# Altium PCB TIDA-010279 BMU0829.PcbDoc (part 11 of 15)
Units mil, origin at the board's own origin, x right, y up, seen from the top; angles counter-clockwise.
Board outline 11269.69 x 4438.98 mil, 4 copper layers (Top Layer, Signal Layer 1, Signal Layer 2, Bottom Layer), stack 61.6 mil thick; 1494 components, 725 nets, 3766 pads, 2728 vias.
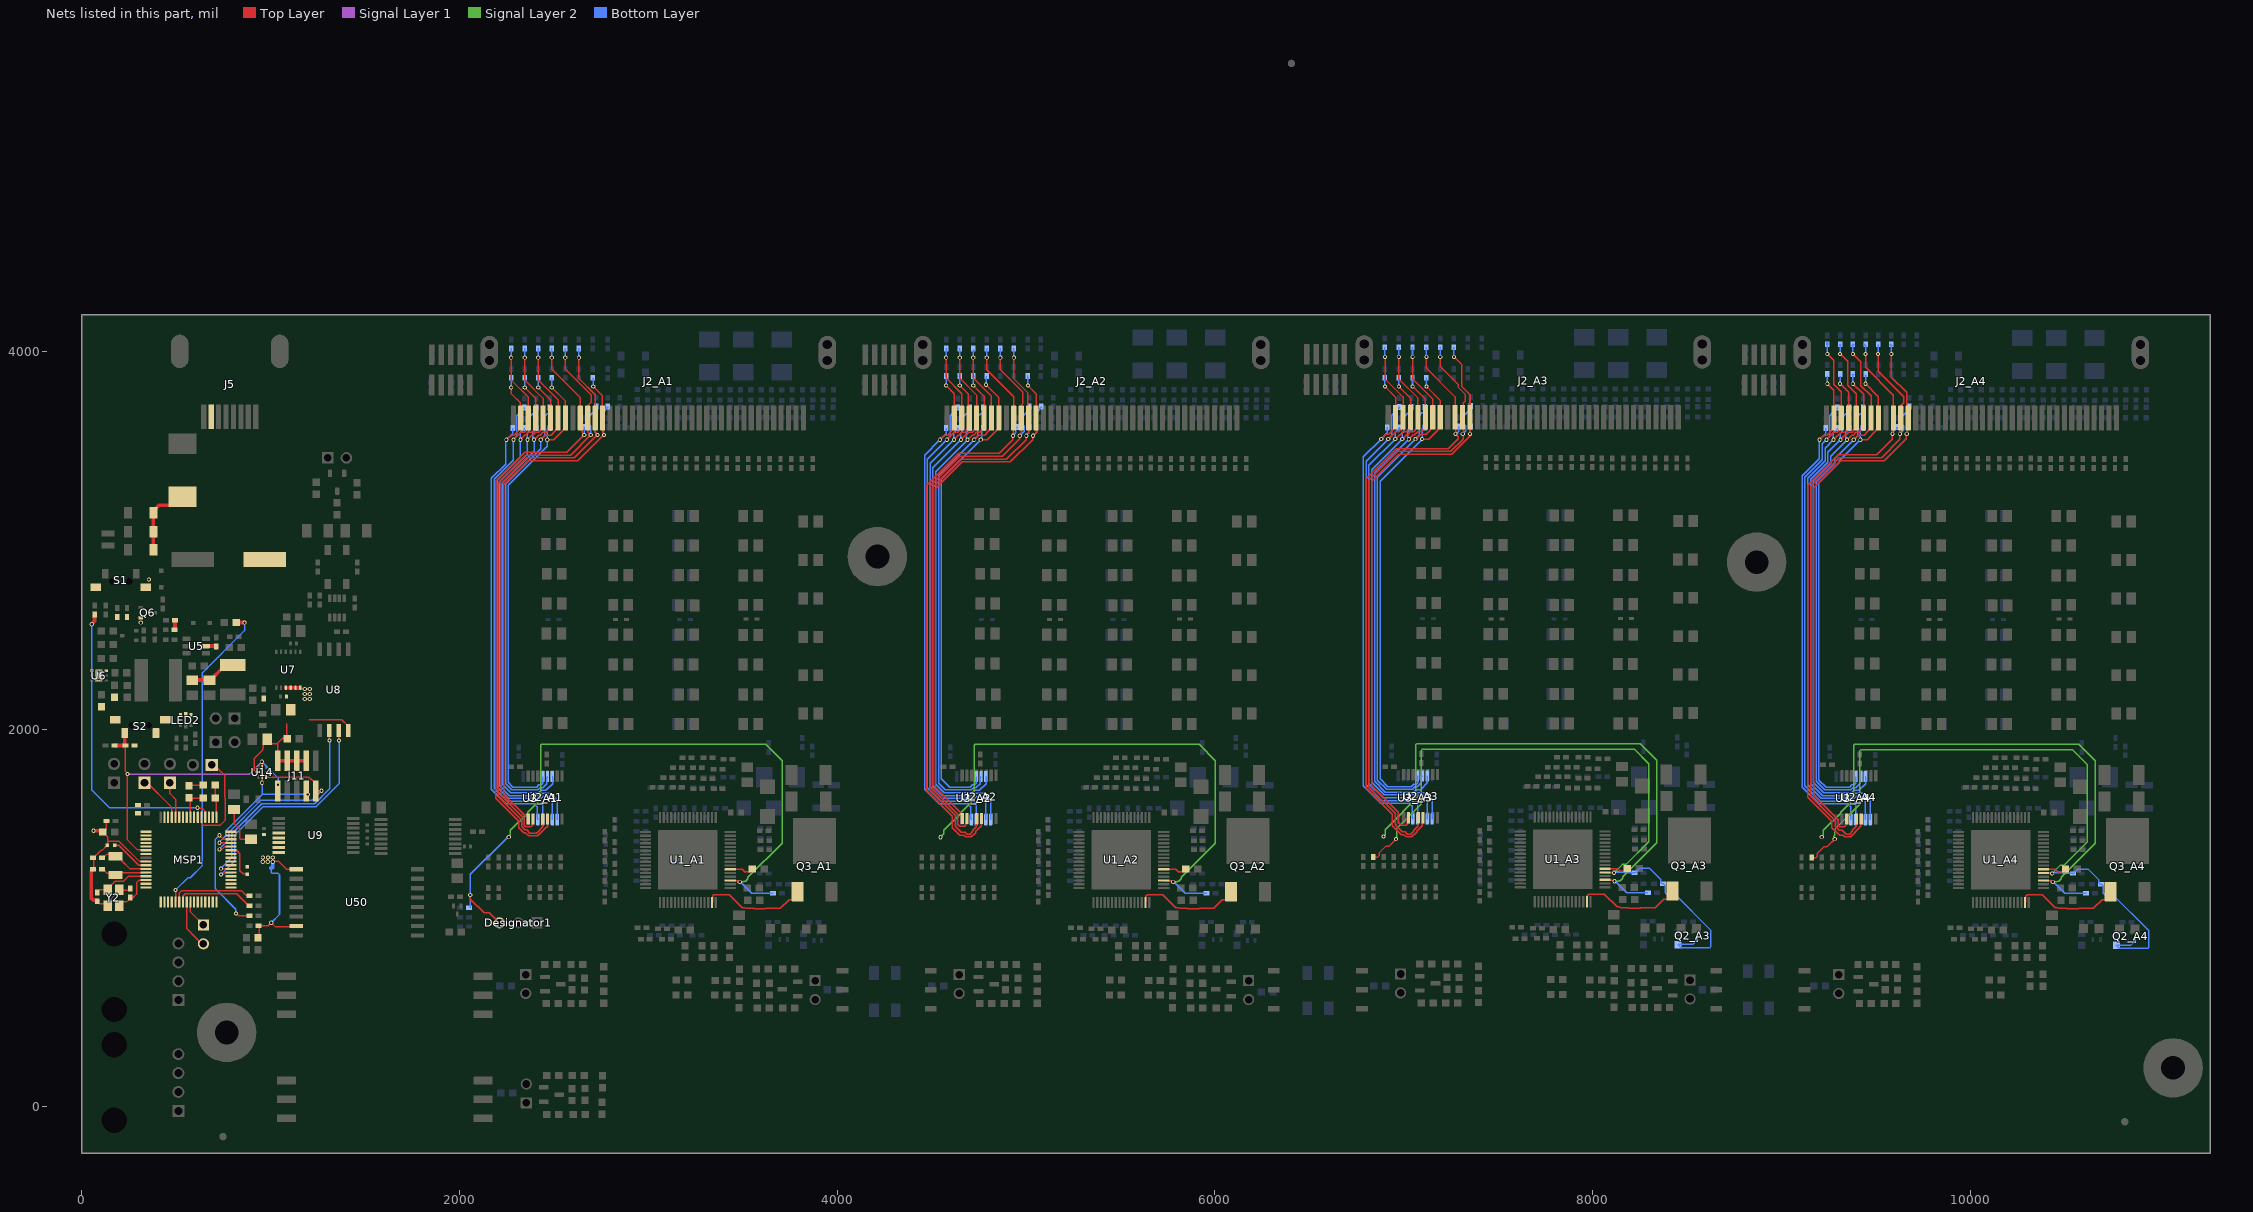
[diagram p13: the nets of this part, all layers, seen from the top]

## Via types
v1: diameter 22.01, hole 12.01, Top Layer to Bottom Layer, tented both sides, 2578 vias
v2: diameter 19.68, hole 7.87, Top Layer to Bottom Layer, tented both sides, 144 vias
v3: diameter 92.52, hole 49.21, Top Layer to Bottom Layer, 4 vias
v4: diameter 19.68, hole 7.87, Top Layer to Bottom Layer, 2 vias

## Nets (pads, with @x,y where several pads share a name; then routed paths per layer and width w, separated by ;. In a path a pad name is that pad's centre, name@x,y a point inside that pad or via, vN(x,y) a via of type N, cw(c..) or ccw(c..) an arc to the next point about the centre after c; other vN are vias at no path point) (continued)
NFAULT/GPIO2_A3: C114_A3.1 Q2_A3.1 R137_A3.2 R150_A3.1 R215_A3.1 U1_A3.53 | length 3719.8
  Top Layer w8: R150_A3.1@6838.78,1322.49 6862.59,1322.49 6868.99,1328.89 6868.99,1344.48 6905.51,1380.99 6922.32,1380.99 v1(6958.65,1417.32) ; U1_A3.53@8065.49,1241.27 8066.57,1240.18 8111.11,1240.18 v1(8112.2,1239.1)
  Signal Layer 2 w8: v1(6958.65,1417.32) 6961.33,1420 6961.33,1443.52 6962.13,1444.32 6962.13,1474.05 7093.31,1605.23 7093.31,1888.09 7098,1892.78 8220.8,1892.78 8296.87,1816.71 8296.87,1403.75 8176.47,1283.35 8156.97,1283.35 8112.72,1239.1 v1(8112.2,1239.1)
  Bottom Layer w8: v1(8112.2,1239.1) 8115.99,1239.1 8120.26,1243.37 8166.42,1243.37 8170.69,1239.1 8220.93,1239.1 C114_A3.1@8221.45,1238.57 8225.39,1238.57 8241.08,1254.26 8241.08,1255.3 8248.03,1262.26 8301.78,1262.26 8359.5,1204.55 8359.5,1188.83 8367.31,1181.02 8375.18,1181.02 8382.99,1173.21 8382.99,1134.2 8392.02,1125.17 8434.93,1125.17 8624.31,935.79 8624.31,846.46 8619.62,841.78 8468.85,841.78 8468.29,842.33 8467.31,842.33 8452.61,857.03 R137_A3.2@8452.61,858.01 8454.55,859.96 8529.58,859.96 8548.94,879.31 Q2_A3.1@8548.94,884.82
NFAULT/GPIO2_A4: C114_A4.1 Q2_A4.1 R137_A4.2 R150_A4.1 R215_A4.1 U1_A4.53 | length 3724.3
  Top Layer w8: R150_A4.1@9159.01,1319.29 9182.82,1319.29 9189.22,1325.68 9189.22,1341.27 9225.74,1377.79 9241.94,1377.79 v1(9281.48,1417.32) ; U1_A4.53@10385.72,1238.06 10386.8,1236.97 10431.34,1236.97 v1(10432.43,1235.89)
  Signal Layer 2 w8: v1(9281.48,1417.32) 9278.8,1420 9278.8,1429.03 9275.52,1432.31 9282.36,1439.16 9282.36,1470.84 9413.54,1602.02 9413.54,1884.88 9418.23,1889.57 10541.03,1889.57 10617.1,1813.51 10617.1,1400.54 10496.7,1280.14 10477.2,1280.14 10432.95,1235.89 v1(10432.43,1235.89)
  Bottom Layer w8: v1(10432.43,1235.89) 10436.22,1235.89 10440.49,1240.16 10486.64,1240.16 10490.92,1235.89 10541.16,1235.89 C114_A4.1@10541.68,1235.37 10545.62,1235.37 10561.31,1251.05 10561.31,1252.09 10568.26,1259.05 10622.01,1259.05 10679.73,1201.34 10679.73,1185.62 10687.54,1177.81 10695.41,1177.81 10703.22,1170 10703.22,1130.99 10712.25,1121.96 10755.16,1121.96 10944.53,932.59 10944.53,843.25 10939.85,838.57 10789.08,838.57 10788.52,839.12 10787.54,839.12 10772.84,853.82 R137_A4.2@10772.84,854.81 10774.78,856.75 10849.81,856.75 10869.17,876.1 Q2_A4.1@10869.17,881.62
NPNB_A1: Q3_A1.1 U1_A1.47 | length 564.5
  Top Layer w7: U1_A1.47@3337.42,1082.55 3339.83,1084.95 3339.83,1115.64 3347.63,1123.45 3429.04,1123.45 3497.52,1054.96 3510.72,1054.96 3515.13,1050.55 3558.12,1050.55 3559.79,1048.88 3620.9,1048.88 3622.57,1050.55 3698.29,1050.55 3744.79,1097.05 3762.29,1097.05 3790.29,1125.04 Q3_A1.1@3790.29,1139.33
NPNB_A2: Q3_A2.1 U1_A2.47 | length 564.5
  Top Layer w7: U1_A2.47@5632.44,1082.55 5634.84,1084.95 5634.84,1115.64 5642.65,1123.45 5724.05,1123.45 5792.54,1054.96 5805.74,1054.96 5810.15,1050.55 5853.13,1050.55 5854.8,1048.88 5915.92,1048.88 5917.59,1050.55 5993.31,1050.55 6039.81,1097.05 6057.31,1097.05 6085.3,1125.04 Q3_A2.1@6085.3,1139.33
NPNB_A3: Q3_A3.1 U1_A3.47 | length 564.5
  Top Layer w7: U1_A3.47@7969.03,1085.75 7971.44,1088.16 7971.44,1118.85 7979.24,1126.66 8060.65,1126.66 8129.14,1058.17 8142.33,1058.17 8146.74,1053.76 8189.73,1053.76 8191.4,1052.09 8252.51,1052.09 8254.18,1053.76 8329.91,1053.76 8376.4,1100.26 8393.9,1100.26 8421.9,1128.25 Q3_A3.1@8421.9,1142.54
NPNB_A4: Q3_A4.1 U1_A4.47 | length 564.5
  Top Layer w7: U1_A4.47@10289.26,1082.55 10291.67,1084.95 10291.67,1115.64 10299.47,1123.45 10380.88,1123.45 10449.37,1054.96 10462.56,1054.96 10466.97,1050.55 10509.96,1050.55 10511.63,1048.88 10572.74,1048.88 10574.41,1050.55 10650.13,1050.55 10696.63,1097.05 10714.13,1097.05 10742.13,1125.04 Q3_A4.1@10742.13,1139.33
PA0: MSP1.33
PA1: MSP1.34
PA2_ROSC: MSP1.42 R229.1 | length 219.4
  Top Layer w8: R229.1@175.65,1385.02 196.48,1385.02 228.37,1353.13 228.37,1352.69 301.61,1279.45 MSP1.42@351.04,1279.45
PA3_LFXIN: C174.2 MSP1.43 Y1.2 | length 287.8
  Top Layer w8: C174.2@106.77,1318.58 114.58,1326.4 123.28,1326.4 123.51,1326.63 123.51,1328.25 131.66,1336.4 179.1,1336.4 194.78,1320.72 200.69,1320.72 212.5,1308.9 212.5,1303 255.74,1259.76 MSP1.43@351.04,1259.76
PA4_LFXOUT: C177.2 MSP1.44 Y1.1 | length 256
  Top Layer w8: C177.2@106.77,1258.51 114.35,1250.93 123.51,1250.93 123.51,1246.99 132.53,1237.98 179.1,1237.98 181.2,1240.08 MSP1.44@351.04,1240.08
PA5_HFXIN: C176.2 MSP1.45 Y2.3 | length 319.5
  Top Layer w8: C176.2@82.99,1135.81 82.99,1139.75 93.52,1150.28 Y2.3@136.77,1150.28 136.77,1155.2 176.18,1194.61 221.42,1194.61 247.2,1220.39 MSP1.45@351.04,1220.39 ; C176.2@84.03,1136.85 89.17,1131.71 C176.2@89.17,1127.78
PA6_HFXOUT: C175.2 MSP1.46 Y2.1 | length 253.5
  Top Layer w8: Y2.1@199.76,1063.66 199.76,1066.54 218.4,1085.18 236.76,1085.18 255.91,1104.33 C175.2@255.91,1108.27 263.28,1100.9 269.67,1107.29 270.71,1107.29 290.28,1126.86 290.28,1187.14 301.95,1198.8 349.13,1198.8 MSP1.46@351.04,1200.71
PA7_CLK-OUT: MSP1.49
PA8_UART1-TX: MSP1.54 R253.1 | length 437.7
  Top Layer w8: MSP1.54@516.39,1083.95 517.31,1084.88 517.31,1132.61 528.26,1143.56 846.31,1143.56 868.64,1121.22 886.24,1121.22 R253.1@890.44,1117.03
PA9_UART1-RX: MSP1.55 R251.2 | length 414.3
  Top Layer w8: MSP1.55@536.08,1084.56 537.98,1086.47 537.98,1117.87 547.79,1127.68 820.38,1127.68 883.86,1064.2 R251.2@887.8,1064.2
PA10_UART0-TX: J16.2 MSP1.56 | length 269.7
  Top Layer w8: MSP1.56@555.76,1084.56 555.76,943.5 601.13,898.13 622.17,877.09 623.55,877.09 637.32,863.32 J16.2@651.13,863.32
PA11_UART0-RX: J16.1 MSP1.57 | length 149.8
  Top Layer w8: MSP1.57@575.45,1084.56 575.45,1032.22 J16.1@644.34,963.32
PA12_CAN-TX: MSP1.5 U8.3 | length 1255
  Top Layer w8: v1(737.05,1229.63) 739.73,1232.31 750.85,1232.31 756.71,1238.17 797.95,1238.17 MSP1.5@799.85,1240.08 ; U8.3@1360.2,1992.78 1361.28,1991.7 1361.28,1940.3 v1(1362.36,1939.22)
  Bottom Layer w8: v1(737.05,1229.63) 737.77,1229.63 810.12,1301.98 810.12,1439.62 959.41,1588.9 1240.1,1588.9 1362.36,1711.16 v1(1362.36,1939.22)
PA13_CAN-RX: MSP1.6 U8.2 | length 1195.7
  Top Layer w8: v1(737.05,1261.26) 738.55,1259.76 MSP1.6@790.01,1259.76 MSP1.6@799.85,1259.76 ; U8.2@1310.2,1992.78 1311.28,1991.7 1311.28,1940.3 v1(1312.36,1939.22)
  Bottom Layer w8: v1@737.87,1263.76 794.18,1320.07 794.18,1395.67 794.25,1395.74 794.25,1446.19 952.83,1604.78 1233.52,1604.78 1312.36,1683.61 v1(1312.36,1939.22)
PA14_TIMH0-C0: MSP1.7
PA15_DAC-OUT: MSP1.8
PA16_OPA1-OUT_ADC1.1: MSP1.9
PA17_OPA1-IN-_ADC1.2: MSP1.10
PA18_OPA1-IN+_ADC1.3_GPAMP-IN-: MSP1.11 R88.2 | length 164.8
  Top Layer w7: MSP1.11@816.93,1358.27 820.62,1358.27 837.86,1341.03 837.86,1250.92 855.64,1233.14 873.16,1233.14 R88.2@875.98,1230.32
PA19_SWDIO: J11.2 MSP1.12 U14.7 | length 1102.6
  Top Layer w8: v1@739.22,1363.16 742.34,1363.16 757.05,1377.87 MSP1.12@799.85,1377.87 ; U14.7@976.29,1746.24 976.29,1745.56 977.21,1744.64 1202.07,1744.64 1210.94,1735.77 1215.02,1735.77 1238.86,1711.93 J11.2@1238.86,1671.57 1240.55,1673.26 v1(1269.65,1673.26)
  Bottom Layer w8: v1@731.07,1369.02 732.67,1369.02 778.37,1414.73 778.37,1452.77 949.62,1624.02 1220.41,1624.02 v1(1269.65,1673.26)
  other v1: 729.38,1363.16
PA20_SWCLK: J11.4 MSP1.13 U14.6 | length 735.6
  Top Layer w8: v1@739.35,1398.21 739.67,1397.88 MSP1.13@766.39,1397.88 ; v1(955.36,1715.6) 956.54,1716.78 956.54,1746.18 U14.6@956.6,1746.24 ; J11.4@1188.86,1645.79 v1(1196.86,1653.79) 1188.86,1661.79 J11.4@1188.86,1671.57
  Bottom Layer w8: v1@732.18,1404.68 762.5,1435 762.5,1460.93 955.36,1653.79 ; v1(955.36,1715.6) 955.36,1653.79 ; v1(1196.86,1653.79) 955.36,1653.79
  other v1: 729.5,1398.21
PA21_VREF-: C172.2 MSP1.17 R223.2 | length 173
  Top Layer w8: R223.2@706.35,1703.38 706.35,1654.17 ; 706.45,1654.07 706.35,1654.17 ; MSP1.17@713.24,1533.38 713.24,1627.59 C172.2@706.35,1634.48 706.35,1654.17
PA22_OPA0-OUT_ADC0.7_GPAMP-OUT_COMP2-IN0+: MSP1.18
PA23_VREF+: C172.1 C173.1 MSP1.24 | length 174.6
  Top Layer w8: C173.1@568.65,1635.47 575.45,1628.67 575.45,1597.08 MSP1.24@575.45,1533.38 ; C173.1@585.29,1629.66 580.46,1634.48 C172.1@643.36,1634.48
PA24_OPA0-IN1-_ADC0.3: MSP1.25
PA25_OPA0-IN1+_ADC0.2: MSP1.26
PA26_OPA0-IN0+_GPAMP-IN+_COMP0-IN0+: MSP1.30
PA27_OPA0-IN0-_COMP0-IN0-_TIMA2_FAL: MSP1.31
PA28_TIMA2_C0: MSP1.35
PA29_TIMG10_C0: MSP1.36
PA30_TIMG10_C1: MSP1.37
PA31_TIMA2_C1: MSP1.39
PB0_SPI1-CS2: MSP1.47
PB1_TIMA1-C1: MSP1.48
PB2_I2C1-SCL: MSP1.50
PB3_I2C1-SDA: MSP1.51
PB4_TIMA1-C0: MSP1.52
PB5: MSP1.53 R220.1 | length 1684.5
  Top Layer w8: v1(496.71,1147.54) 496.71,1086.47 MSP1.53@498.61,1084.56
  Top Layer w20: R220.1@817.14,2564.71 860.85,2564.71 861.89,2563.67 v1(862.43,2563.67)
  Bottom Layer w8: v1(496.71,1147.54) 562.05,1212.89 574.4,1212.89 637.07,1275.56 637.07,2296.11 862.65,2521.69 862.65,2529.55 862.43,2529.77 v1(862.43,2563.67)
PB6_SPI1-CS0: MSP1.58
PB7_SPI1-POCI: MSP1.59
PB8_SPI1-PICO: MSP1.60
PB9_SPI1-SCK: MSP1.61
PB10_TIMG0-C0: MSP1.62
PB11_TIMG0-C1: MSP1.63
PB12_TIMA0-C2_TIMA1-FAL: MSP1.64
PB13_TIMA0-C3: MSP1.1
PB14_TIMG10_IDX: MSP1.2
PB15_UART2-TX_TIMG1-C0: MSP1.3
PB16_UART2-RX_TIMG1-C1: MSP1.4
PB17_ADC1.4_SPI1-CS1: MSP1.14 R250.2 | length 626.2
  Top Layer w8: v1(729.78,1438.25) 750.78,1417.24 MSP1.14@790.01,1417.24 MSP1.14@799.85,1417.24 ; v1(816.93,1023.62) 818.02,1023.62 828.62,1013.02 R250.2@889.93,1013.02
  Bottom Layer w8: v1(729.78,1438.25) 706.5,1414.97 706.5,1155.76 815.63,1046.63 815.63,1024.92 v1(816.93,1023.62)
PB18_ADC1.5: MSP1.15
PB19_OPA1-IN+_ADC1.6: MSP1.16
PB20_TIMA0-C2: MSP1.19
PB21: MSP1.20 R216.1 | length 1599.7
  Top Layer w8: v1(613.43,1583.56) 615.84,1581.15 637.82,1581.15 653.15,1565.82 MSP1.20@653.15,1544.26
  Top Layer w20: v1(52.79,2554.96) 52.79,2555.5 68.17,2570.88 68.17,2600.49 R216.1@69.98,2602.3
  Bottom Layer w8: v1(52.79,2554.96) 52.45,2554.62 52.45,1678.93 147.83,1583.56 v1(613.43,1583.56)
PB22: J17.1 MSP1.21 | length 496
  Top Layer w8: MSP1.21@634.5,1533.38 635.32,1532.57 635.32,1498.94 642.28,1491.98 734.59,1491.98 759.07,1516.46 759.07,1519.83 756.61,1755.52 J17.1@696.25,1815.89
PB23_TIMA0-FAL: MSP1.22
PB24_ADC0.5_COMP1-IN1+: MSP1.23
PB25_ADC0.4_TIMA2-FAL: MSP1.27
PB26: J18.1 MSP1.28 | length 199.6
  Top Layer w8: J18.1@467.18,1720.72 467.18,1658.6 496.71,1629.07 MSP1.28@496.71,1533.38
PB27: J20.1 MSP1.29 | length 247.3
  Top Layer w8: J20.1@339.57,1723.71 475.84,1587.43 475.84,1534.56 MSP1.29@477.02,1533.38
PGND: C167.2 C168.2 C169.2 C170.2 C171.2 C173.2 C174.1 C175.1 C176.1 C177.1 C178.2 C179.2 C180.2 C181.2 C183.2 C184.2 C185.2 C186.2 C196.2 C197.2 C198.2 C199.2 C201.1 C205.2 C206.1 C207.2 C213.2 C214.1 C215.2 C216.2 CO1.2 D13.1 J5.1 J11.3 J11.5 J11.7 J11.9 LED2.1 LED2.2 LED2.3 MSP1.41 Q6.2 R88.1 R219.1 R223.1 R229.2 R236.1 R244.1 S1.1 S1.2 S2.1 S2.2 S2.3 U5.2 U6.3 U6.4 U6.7@91.18,2283.19 U7.3 U7.4 U7.5 U7.6 U8.4 U9.4 U9.5 U9.6 U9.7 U9.8 U14.4 U50.9 U50.15 Y2.2 Y2.4 | length 3961.3
  Top Layer w8: C177.1@64.52,1258.74 64.52,1313.59 C174.1@59.52,1318.58 63.46,1318.58 71.27,1326.4 71.27,1327.44 101.08,1357.25 108.01,1357.25 135.3,1384.53 R229.2@135.3,1385.02 137.28,1387.01 137.28,1402.05 ; C176.1@82.99,1088.56 82.99,1084.63 90.8,1076.82 94.74,1076.82 95.87,1075.69 124.74,1075.69 Y2.4@136.77,1063.66 155.41,1082.3 155.41,1101 Y2.2@199.76,1145.35 ; C167.2@112.12,1454.71 C167.2@113.1,1454.71 ; C168.2@130.67,1513.33 130.67,1472.27 C167.2@113.1,1454.71 ; Y2.2@199.76,1150.28 203.38,1146.66 248.09,1146.66 255.91,1154.47 C175.1@255.91,1155.51 ; MSP1.41@351.04,1299.13 305.47,1299.13 197.86,1406.74 141.97,1406.74 137.28,1402.05 ; C173.2@568.65,1699.45 572.59,1703.38 R223.1@643.36,1703.38 ; C186.2@807.09,1574.17 807.09,1500.01 836.61,1470.48 836.61,1422.01 841.3,1417.32 C213.2@885.63,1417.32 ; U14.4@931.01,1772.82 929.11,1774.72 923.2,1774.72 913.45,1784.47 913.45,1844.53 959.77,1890.85 959.77,1901.87 961.76,1903.85 961.76,1925.08 C185.2@982.76,1946.08 982.69,1946.01 982.69,1943.87 1003.69,1922.87 1033.99,1922.87 1038.86,1927.74 ; v1@1013.78,1299.21 1043.31,1299.21 1084.84,1257.68 U50.9@1135.69,1257.68 ; J11.9@1038.86,1831.81 1038.86,1927.74 ; 1085.87,2027.87 1085.87,1963.43 1074.55,1963.43 1073.83,1962.71 1073.83,1951.39 1073.1,1950.67 1061.79,1950.67 1038.86,1927.74 ; C201.1@1087.8,1948.73 C201.1@1088.79,1948.73 ; C205.2@1107.02,2102.33 C205.2@1127.44,2081.91 ; U50.15@1135.69,957.68 1132.74,954.72 1023.62,954.72 v1(1003.94,974.41) 1003.12,974.41 987.26,958.55 937.69,958.55 939.4,956.84 939.4,900.17 C216.2@933.76,894.53 ; 1205.98,2049.94 1376.66,2049.94 1410.2,2016.4 U8.4@1410.2,1992.78 ; C167.2@113.1,1454.71 127.8,1440.01 127.8,1439.02 137.28,1429.54 137.28,1402.05 ; C216.2@933.76,894.53 933.76,893.55 919.06,878.85 918.08,878.85 C216.2@933.76,894.53
  Top Layer w20: C177.1@59.52,1258.51 57.71,1256.7 53.77,1256.7 53.77,1247.99 50,1244.22 50,1106.03 61.72,1094.31 81.18,1094.31 82.99,1092.5 C176.1@82.99,1084.63 ; v1(62.49,1461.71) 62.88,1461.32 105.5,1461.32 C167.2@112.12,1454.71 ; C198.2@104.46,2127.03 C198.2@104.46,2128.02 ; S1.2@339.57,2751.97 343.61,2751.97 S1.2@353.29,2761.65 ; C181.2@379.29,2949.24 C180.2@379.29,3034.96 ; C180.2@390.94,3023.31 C180.2@379.29,3034.96 ; C199.2@492.13,2527.01 492.29,2527.01 494.1,2528.82 R244.1@494.1,2576.52 ; D13.1@533.47,3230.1 488.47,3185.1 408.89,3185.1 379.29,3155.5 C179.2@379.29,3145.66 C180.2@379.29,3044.8 C180.2@379.29,3034.96 ; C183.2@597.29,2260.61 682.54,2260.61 749.24,2327.31 C184.2@749.24,2351.14 ; U5.2@657.92,2440.38 U5.2@657.24,2439.69 700.07,2439.69 R219.1@707.52,2432.24 ; R219.1@711.87,2436.59 711.87,2432.91 R219.1@713.68,2431.1 ; J11.9@1038.86,1831.81 J11.7@1088.86,1831.81 J11.5@1138.86,1831.81 J11.3@1188.86,1831.81 ; U7.3@1080.72,2219.34 U7.4@1106.31,2219.34 U7.5@1131.9,2219.34 ; U7.5@1132.55,2216.98 1155.99,2216.98 1155.99,2217.85 U7.6@1157.49,2219.34
  Bottom Layer w8: 1002.85,1264.08 1002.85,1240.99 1006.08,1237.76 1039.07,1237.76 1047.2,1229.63 1047.2,1018.47 1003.94,975.2 v1(1003.94,974.41)
  Bottom Layer w20: 1002.85,1264.08 1004.66,1265.89 1011.12,1265.89 v1(1011.12,1297.72)
  other v1: 958.52,1297.72 985.26,1297.72 958.97,1320.72 985.71,1320.72 1011.57,1320.72 1181.11,2159.75 1207.01,2159.75 1181.11,2185.61 1207.01,2185.61 1181.11,2212.35 1207.01,2212.35 312.27,2563.67 355.54,2792.19
  other v4: 91.18,2261.54 91.18,2304.84
R\S\T\: C171.1 J11.10 MSP1.38 R214.1 S2.4 U14.2 | length 1686.3
  Top Layer w8: S2.4@225.34,1995.66 S2.4@226.83,1994.17 ; C171.1@231.49,1913.14 231.49,1776.51 242.4,1765.6 v1(242.4,1761.81) 242.4,1412.93 295.23,1360.09 349.13,1360.09 MSP1.38@351.04,1358.19 ; v1(953.81,1826.69) 953.81,1822.9 956.6,1820.11 U14.2@956.6,1799.39
  Top Layer w20: R214.1@173.35,1913.14 C171.1@229.4,1913.14 ; S2.4@227.59,1979.07 227.59,1914.95 C171.1@229.4,1913.14 ; C171.1@231.49,1913.14 C171.1@229.4,1913.14
  Signal Layer 1 w8: v1(242.4,1761.81) 888.93,1761.81 v1(953.81,1826.69)
  Bottom Layer w8: v1(953.81,1826.69) 1039.52,1740.99 v1(1039.52,1705.6)
REF_CAP_A1: C64_A1.2 U1_A1.54 | length 130.9
  Top Layer w7: U1_A1.54@3433.88,1257.74 3470.79,1257.74 3471.31,1258.27 3498.29,1258.27 3513.61,1242.94 3515.31,1244.64 3535.98,1244.64 C64_A1.2@3551.18,1259.84
REF_CAP_A2: C64_A2.2 U1_A2.54 | length 130.9
  Top Layer w7: U1_A2.54@5728.89,1257.74 5765.81,1257.74 5766.33,1258.27 5793.3,1258.27 5808.63,1242.94 5810.33,1244.64 5831,1244.64 C64_A2.2@5846.2,1259.84
REF_CAP_A3: C64_A3.2 U1_A3.54 | length 130.9
  Top Layer w7: U1_A3.54@8065.49,1260.95 8102.4,1260.95 8102.93,1261.48 8129.9,1261.48 8145.22,1246.15 8146.92,1247.85 8167.59,1247.85 C64_A3.2@8182.79,1263.05
REF_CAP_A4: C64_A4.2 U1_A4.54 | length 130.9
  Top Layer w7: U1_A4.54@10385.72,1257.74 10422.63,1257.74 10423.16,1258.27 10450.13,1258.27 10465.45,1242.94 10467.15,1244.64 10487.82,1244.64 C64_A4.2@10503.02,1259.84
RX/GPIO0_A1: Designator1.3 R208.1 R257_A1.1 U1_A1.51 | length 3566.6
  Top Layer w7: v1(2057.09,1122.05) 2057.09,1100.24 2130.27,1027.06 2158.77,1027.06 2194.41,991.41 2211.89,991.41 Designator1.3@2214.57,994.09 ; U1_A1.51@3433.88,1198.69 3435.31,1197.25 3473.9,1197.25 3480.02,1191.13 v1(3484.09,1191.13)
  Signal Layer 2 w7: v1(2260.93,1427.8) 2269.87,1436.74 2269.87,1463.54 2361.83,1555.5 2361.83,1558.46 2431.45,1628.08 2431.45,1915.72 2435.55,1919.82 3620.72,1919.82 3707.74,1832.8 3707.74,1395.18 3527.64,1215.08 3527.64,1208.01 3514.53,1194.9 3509.09,1194.9 3505.59,1191.4 3484.36,1191.4 v1(3484.09,1191.13)
  Bottom Layer w7: R208.1@2055.12,1053.15 2057.09,1055.12 v1(2057.09,1122.05) 2057.09,1230.32 2249.54,1422.77 2251.84,1422.77 2256.87,1427.8 v1(2260.93,1427.8) ; v1(3484.09,1191.13) 3487.28,1191.13 3547.42,1130.99 R257_A1.1@3660.84,1130.99
RX/GPIO0_A2: R257_A2.1 U1_A2.51 | length 2881.8
  Top Layer w7: U1_A2.51@5728.89,1198.69 5730.33,1197.25 5768.92,1197.25 5775.04,1191.13 v1(5779.1,1191.13)
  Signal Layer 2 w7: v1(4547.23,1427.16) v1(4547.23,1427.16) 4564.88,1444.87 4564.88,1463.54 4656.84,1555.5 4656.84,1558.46 4726.47,1628.08 4726.47,1915.72 4730.57,1919.82 5915.73,1919.82 6002.75,1832.8 6002.75,1395.18 5822.65,1215.08 5822.65,1208.01 5809.54,1194.9 5804.11,1194.9 5800.61,1191.4 5779.37,1191.4 v1(5779.1,1191.13)
  Bottom Layer w7: v1(5779.1,1191.13) 5782.3,1191.13 5842.44,1130.99 R257_A2.1@5955.86,1130.99
RX/GPIO0_A3: R257_A3.1 U1_A3.51 | length 2877.5
  Top Layer w7: U1_A3.51@8065.49,1201.9 8066.92,1200.46 8105.52,1200.46 8111.64,1194.34 v1(8115.7,1194.34)
  Signal Layer 2 w7: v1(6892.54,1431.01) 6901.48,1439.95 6901.48,1466.75 6993.44,1558.71 6993.44,1561.67 7063.07,1631.29 7063.07,1918.92 7067.17,1923.02 8252.33,1923.02 8339.35,1836.01 8339.35,1398.38 8159.25,1218.28 8159.25,1211.22 8146.14,1198.11 8140.7,1198.11 8137.2,1194.61 8115.97,1194.61 v1(8115.7,1194.34)
  Bottom Layer w7: v1(8115.7,1194.34) 8118.89,1194.34 8179.04,1134.2 R257_A3.1@8292.46,1134.2
RX/GPIO0_A4: R257_A4.1 U1_A4.51 | length 2877.5
  Top Layer w7: U1_A4.51@10385.72,1198.69 10387.15,1197.25 10425.75,1197.25 10431.87,1191.13 v1(10435.93,1191.13)
  Signal Layer 2 w7: v1(9212.77,1427.8) 9221.71,1436.74 9221.71,1463.54 9313.67,1555.5 9313.67,1558.46 9383.3,1628.08 9383.3,1915.72 9387.4,1919.82 10572.56,1919.82 10659.58,1832.8 10659.58,1395.18 10479.48,1215.08 10479.48,1208.01 10466.37,1194.9 10460.93,1194.9 10457.43,1191.4 10436.2,1191.4 v1(10435.93,1191.13)
  Bottom Layer w7: v1(10435.93,1191.13) 10439.12,1191.13 10499.27,1130.99 R257_A4.1@10612.69,1130.99
TS1_A1: C136_A1.1 J2_A1.1 R214_A1.1 U3_A1.5 | length 2636.4
  Top Layer w7: v1(2248.36,3532.1) 2273.04,3556.78 2288.89,3556.78 2310.69,3578.58 2310.69,3581.73 2324.91,3595.94 J2_A1.1@2324.91,3647.12
  Top Layer w8: v1@2273.62,3799.21 2273.62,3776.7 2322.83,3727.49 J2_A1.1@2322.83,3710.63
  Bottom Layer w7: C136_A1.1@2280.98,3593.93 2280.98,3564.72 2245.49,3529.23 2245.49,3521.89 2244.09,3520.5 2244.09,3403.45 2169.5,3328.86 2169.5,1680.37 2246.35,1603.52 2397.77,1603.52 2412.94,1588.35 2412.94,1528.73 2415.13,1526.54 U3_A1.5@2415.13,1520.2
  Bottom Layer w8: v1@2273.62,3799.21 R214_A1.1@2273.62,3860.24
  other v1: 2273.62,3809.06
TS1_A2: C136_A2.1 J2_A2.1 R214_A2.1 U3_A2.5 | length 2655
  Top Layer w7: v1(4543.38,3532.1) 4568.05,3556.78 4583.9,3556.78 4605.71,3578.58 4605.71,3581.73 4619.93,3595.94 J2_A2.1@4619.93,3647.12
  Top Layer w8: v1(4576.77,3818.9) 4619.93,3775.74 4619.93,3704.57 J2_A2.1@4616.14,3700.79
  Bottom Layer w7: C136_A2.1@4575.99,3593.93 4575.99,3564.72 v1(4543.38,3532.1) 4462.31,3451.03 4462.31,1682.58 4541.37,1603.52 4692.79,1603.52 4707.96,1588.35 4707.96,1528.73 4710.14,1526.54 U3_A2.5@4710.14,1520.2
  Bottom Layer w8: v1(4576.77,3818.9) R214_A2.1@4576.77,3868.11
TS1_A3: C136_A3.1 J2_A3.1 R214_A3.1 U3_A3.5 | length 2648.5
  Top Layer w7: v1(6879.97,3535.31) 6904.65,3559.98 6920.5,3559.98 6942.31,3581.79 6942.31,3584.93 6956.52,3599.15 J2_A3.1@6956.52,3650.33
  Top Layer w8: v1(6900.4,3813.3) 6956.52,3757.18 6956.52,3711.29 6957.18,3710.63 J2_A3.1@6958.66,3710.63
  Bottom Layer w7: C136_A3.1@6912.59,3597.14 6912.59,3567.93 v1(6879.97,3535.31) 6785.65,3440.98 6785.65,1699.05 6877.97,1606.73 7029.39,1606.73 7044.56,1591.56 7044.56,1531.94 7046.74,1529.75 U3_A3.5@7046.74,1523.41
  Bottom Layer w8: v1@6899.61,3818.9 6900,3819.29 6900,3859.84 R214_A3.1@6899.61,3860.24
TS1_A4: C136_A4.1 J2_A4.1 R214_A4.1 U3_A4.5 | length 2660.8
  Top Layer w7: v1(9200.2,3532.1) 9224.88,3556.78 9240.73,3556.78 9262.54,3578.58 9262.54,3581.73 9276.75,3595.94 J2_A4.1@9276.75,3647.12 ; v1(9242.13,3828.74) 9276.75,3794.11 J2_A4.1@9276.75,3705.89
  Top Layer w12: J2_A4.1@9271.65,3700.79 J2_A4.1@9276.75,3705.89
  Bottom Layer w7: C136_A4.1@9232.82,3593.93 9232.82,3564.72 v1(9200.2,3532.1) 9200.2,3432.49 9108.48,3340.76 9108.48,1693.24 9198.2,1603.52 9349.62,1603.52 9364.79,1588.35 9364.79,1528.73 9366.97,1526.54 U3_A4.5@9366.97,1520.2 ; v1(9242.13,3828.74) R214_A4.1@9242.13,3868.11
TS2_A1: C130_A1.1 J2_A1.22 R213_A1.1 U3_A1.4 | length 2970
  Top Layer w7: v1(2285.54,3532.1) 2324.23,3570.79 2342.27,3570.79 2350.06,3578.58 2350.06,3581.73 2364.28,3595.94 J2_A1.22@2364.28,3647.12
  Top Layer w8: 2273.62,3848.41 2364.28,3757.75 2364.28,3693.02 J2_A1.22@2362.2,3690.94 ; 2273.62,3848.43 v1(2273.62,3966.54)
  Bottom Layer w7: C130_A1.1@2343.97,3702.2 2343.97,3698.26 2304.35,3658.65 2304.35,3550.91 v1(2285.54,3532.1) 2285.54,3423.86 2184.38,3322.7 2184.38,1686.53 2252.51,1618.4 2430.25,1618.4 2440.72,1607.93 U3_A1.4@2440.72,1520.2
  Bottom Layer w8: v1@2273.62,3976.38 R213_A1.1@2273.62,4015.75
TS2_A2: C130_A2.1 J2_A2.22 R213_A2.1 U3_A2.4 | length 2969.2
  Top Layer w7: v1(4580.56,3532.1) 4619.24,3570.79 4637.29,3570.79 4645.08,3578.58 4645.08,3581.73 4659.3,3595.94 J2_A2.22@4659.3,3647.12
  Top Layer w8: v1(4576.77,3966.54) 4576.77,3858.25 4659.3,3775.73 4659.3,3704.57 J2_A2.22@4655.51,3700.79
  Bottom Layer w7: C130_A2.1@4638.98,3702.2 4638.98,3698.26 4599.37,3658.65 4599.37,3550.91 v1(4580.56,3532.1) 4477.19,3428.73 4477.19,1688.74 4547.53,1618.4 4725.27,1618.4 4735.74,1607.93 U3_A2.4@4735.74,1520.2
  Bottom Layer w8: v1(4576.77,3966.54) R213_A2.1@4576.77,4015.75
TS2_A3: C130_A3.1 J2_A3.22 R213_A3.1 U3_A3.4 | length 2982.1
  Top Layer w7: v1(6917.15,3535.31) 6955.84,3574 6973.88,3574 6981.68,3581.79 6981.68,3584.93 6995.89,3599.15 J2_A3.22@6995.89,3650.33
  Top Layer w8: v1(6900.4,3970.78) 6900.4,3854.06 6995.89,3758.57 6995.89,3711.29 6995.23,3710.63 J2_A3.22@6988.19,3710.63
  Bottom Layer w7: C130_A3.1@6975.58,3705.41 6975.58,3701.47 6935.96,3661.85 6935.96,3554.12 v1(6917.15,3535.31) 6800.52,3418.68 6800.52,1705.21 6884.13,1621.61 7061.87,1621.61 7072.33,1611.14 U3_A3.4@7072.33,1523.41
  Bottom Layer w8: v1@6899.61,3976.38 6900,3976.78 6900,4021.26 R213_A3.1@6899.61,4021.65
TS2_A4: C130_A4.1 J2_A4.22 R213_A4.1 U3_A4.4 | length 3014.2
  Top Layer w7: v1(9237.38,3532.1) 9276.07,3570.79 9294.11,3570.79 9301.91,3578.58 9301.91,3581.73 9316.12,3595.94 J2_A4.22@9316.12,3647.12 ; v1(9242.13,3986.22) 9276.19,3952.15 9276.19,3826.98 9316.12,3787.05 J2_A4.22@9316.12,3695.69
  Top Layer w12: J2_A4.22@9316.12,3695.69 J2_A4.22@9320.87,3690.94
  Bottom Layer w7: v1(9242.13,3986.22) R213_A4.1@9242.13,4037.4 ; C130_A4.1@9295.81,3702.2 9295.81,3698.26 9256.19,3658.65 9256.19,3550.91 9215.08,3509.8 9215.08,3426.33 9123.35,3334.6 9123.35,1699.4 9204.36,1618.4 9382.1,1618.4 9392.56,1607.93 U3_A4.4@9392.56,1520.2
  Bottom Layer w12: R213_A4.1@9242.13,4037.4 R213_A4.1@9242.13,4045.28
TS3_A1: C126_A1.1 J2_A1.2 R212_A1.1 U3_A1.2 | length 2744
  Top Layer w7: v1(2322.72,3532.1) 2346.53,3555.91 2348.43,3555.91 2363.31,3570.79 2381.64,3570.79 2389.43,3578.58 2389.43,3581.73 2403.65,3595.94 J2_A1.2@2403.65,3647.12
  Top Layer w8: v1(2345.33,3809.06) 2403.65,3750.74 2403.65,3702.86 J2_A1.2@2401.57,3700.79
  Bottom Layer w7: C126_A1.1@2343.47,3593.93 2343.47,3590 2322.72,3569.24 2322.72,3440.01 2199.25,3316.54 2199.25,1692.69 2258.67,1633.27 2432.77,1633.27 2445.19,1645.69 2473.36,1645.69 2491.9,1627.15 U3_A1.2@2491.9,1520.2
  Bottom Layer w8: v1@2342.52,3809.06 2345.33,3811.87 R212_A1.1@2345.33,3860.24
TS3_A2: C126_A2.1 J2_A2.2 R212_A2.1 U3_A2.2 | length 2738.1
  Top Layer w7: v1(4617.73,3532.1) 4641.55,3555.91 4643.45,3555.91 4658.32,3570.79 4676.66,3570.79 4684.45,3578.58 4684.45,3581.73 4698.67,3595.94 J2_A2.2@4698.67,3647.12
  Top Layer w8: v1(4648.48,3818.9) 4694.88,3772.5 J2_A2.2@4694.88,3710.63
  Bottom Layer w7: C126_A2.1@4638.49,3593.93 4638.49,3590 4617.73,3569.24 v1(4617.73,3532.1) 4492.06,3406.42 4492.06,1694.9 4553.69,1633.27 4727.79,1633.27 4740.21,1645.69 4768.37,1645.69 4786.92,1627.15 U3_A2.2@4786.92,1520.2
  Bottom Layer w8: R212_A2.1@4645.67,3868.11 4648.48,3865.3 v1(4648.48,3818.9)
TS3_A3: C126_A3.1 J2_A3.2 R212_A3.1 U3_A3.2 | length 2755.6
  Top Layer w7: v1(6954.33,3535.31) 6978.15,3559.12 6980.04,3559.12 6994.92,3574 7013.25,3574 7021.05,3581.79 7021.05,3584.93 7035.26,3599.15 J2_A3.2@7035.26,3650.33
  Top Layer w8: v1(6973.52,3813.3) 7035.26,3751.55 7035.26,3708.49 J2_A3.2@7027.56,3700.79
  Bottom Layer w7: C126_A3.1@6975.09,3597.14 6975.09,3593.2 6954.33,3572.45 v1(6954.33,3535.31) 6815.39,3396.37 6815.39,1711.37 6890.29,1636.48 7064.38,1636.48 7076.8,1648.9 7104.97,1648.9 7123.51,1630.36 U3_A3.2@7123.51,1523.41
  Bottom Layer w8: v1@6968.5,3818.9 6972.72,3823.12 R212_A3.1@6972.72,3860.24
TS3_A4: C126_A4.1 J2_A4.2 R212_A4.1 U3_A4.2 | length 2767.8
  Top Layer w7: v1(9274.56,3532.1) 9298.38,3555.91 9300.27,3555.91 9315.15,3570.79 9333.48,3570.79 9341.28,3578.58 9341.28,3581.73 9355.49,3595.94 J2_A4.2@9355.49,3647.12 ; v1(9309.62,3828.74) 9355.49,3782.87 J2_A4.2@9355.49,3695.69
  Top Layer w12: J2_A4.2@9355.49,3695.69 J2_A4.2@9360.24,3690.94
  Bottom Layer w7: C126_A4.1@9295.32,3593.93 9295.32,3590 9274.56,3569.24 v1(9274.56,3532.1) 9229.95,3487.49 9229.95,3420.16 9138.23,3328.44 9138.23,1705.56 9210.52,1633.27 9384.61,1633.27 9397.03,1645.69 9425.2,1645.69 9443.74,1627.15 U3_A4.2@9443.74,1520.2 ; v1@9311.02,3830.15 R212_A4.1@9311.02,3868.11
  Bottom Layer w12: v1(9309.62,3828.74) v1@9311.02,3830.15
TS4_A1: C121_A1.1 J2_A1.23 R211_A1.1 U3_A1.1 | length 3078.7
  Top Layer w7: v1(2359.9,3532.1) 2383.71,3555.91 2387.8,3555.91 2402.68,3570.79 2421.01,3570.79 2428.8,3578.58 2428.8,3581.73 2443.02,3595.94 J2_A1.23@2443.02,3647.12
  Top Layer w8: v1@2342.52,3966.54 2345.33,3963.72 2345.33,3848.41 2443.02,3750.72 2443.02,3683.18 J2_A1.23@2440.94,3681.1
  Bottom Layer w7: C121_A1.1@2406.66,3702.2 2405.97,3701.51 2405.97,3675.66 2400.11,3669.8 2388.83,3669.8 2368.16,3649.13 2368.16,3574.97 2359.39,3566.2 2359.39,3532.61 v1(2359.9,3532.1) 2359.9,3456.15 2214.13,3310.38 2214.13,1698.86 2264.84,1648.15 2426.61,1648.15 2439.03,1660.57 2479.52,1660.57 2517.49,1622.59 U3_A1.1@2517.49,1520.2
  Bottom Layer w8: v1@2342.52,3966.54 2345.33,3969.35 R211_A1.1@2345.33,4015.75
  other v1: 2345.33,3966.54
TS4_A2: C121_A2.1 J2_A2.23 R211_A2.1 U3_A2.1 | length 3057
  Top Layer w7: v1(4654.91,3532.1) 4678.73,3555.91 4682.82,3555.91 4697.69,3570.79 4716.03,3570.79 4723.82,3578.58 4723.82,3581.73 4738.04,3595.94 J2_A2.23@4738.04,3647.12
  Top Layer w8: v1(4648.48,3966.54) 4648.48,3858.25 4738.04,3768.7 4738.04,3704.57 J2_A2.23@4734.25,3700.79
  Bottom Layer w7: C121_A2.1@4701.68,3702.2 4700.98,3701.51 4700.98,3675.66 4695.13,3669.8 4683.84,3669.8 4663.17,3649.13 4663.17,3574.97 4654.4,3566.2 4654.4,3532.61 v1(4654.91,3532.1) 4506.93,3384.12 4506.93,1701.06 4559.85,1648.15 4721.63,1648.15 4734.05,1660.57 4774.53,1660.57 4812.51,1622.59 U3_A2.1@4812.51,1520.2
  Bottom Layer w8: R211_A2.1@4645.67,4015.75 4648.48,4012.94 v1(4648.48,3966.54)
TS4_A3: C121_A3.1 J2_A3.23 R211_A3.1 U3_A3.1 | length 3069.5
  Top Layer w7: v1(6991.51,3535.31) 7015.33,3559.12 7019.41,3559.12 7034.29,3574 7052.62,3574 7060.42,3581.79 7060.42,3584.93 7074.63,3599.15 J2_A3.23@7074.63,3650.33
  Top Layer w8: v1(6973.52,3970.78) 6973.52,3854.06 7074.63,3752.95 7074.63,3711.29 7073.97,3710.63 J2_A3.23@7066.93,3710.63
  Bottom Layer w7: C121_A3.1@7038.28,3705.41 7037.58,3704.71 7037.58,3678.87 7031.72,3673.01 7020.44,3673.01 6999.77,3652.34 6999.77,3578.18 6991,3569.41 6991,3535.82 v1(6991.51,3535.31) 6830.27,3374.07 6830.27,1717.53 6896.45,1651.35 7058.22,1651.35 7070.64,1663.77 7111.13,1663.77 7149.1,1625.8 U3_A3.1@7149.1,1523.41
  Bottom Layer w8: v1@6968.5,3976.38 6972.72,3980.6 R211_A3.1@6972.72,4021.65
TS4_A4: C121_A4.1 J2_A4.23 R211_A4.1 U3_A4.1 | length 3103.4
  Top Layer w7: v1(9309.62,3986.22) 9349.31,3946.53 9349.31,3821.36 9394.86,3775.8 J2_A4.23@9394.86,3686.2 ; v1(9311.74,3532.1) 9335.56,3555.91 9339.64,3555.91 9354.52,3570.79 9372.85,3570.79 9380.65,3578.58 9380.65,3581.73 9394.86,3595.94 J2_A4.23@9394.86,3647.12
  Top Layer w12: J2_A4.23@9389.76,3681.1 J2_A4.23@9394.86,3686.2
  Bottom Layer w7: v1(9309.62,3986.22) R211_A4.1@9309.62,4034.03 ; C121_A4.1@9358.51,3702.2 9357.81,3701.51 9357.81,3675.66 9351.95,3669.8 9340.67,3669.8 9320,3649.13 9320,3574.97 9311.23,3566.2 9311.23,3532.61 v1(9311.74,3532.1) 9244.82,3465.18 9244.82,3414 9153.1,3322.28 9153.1,1711.72 9216.68,1648.15 9378.45,1648.15 9390.87,1660.57 9431.36,1660.57 9469.33,1622.59 U3_A4.1@9469.33,1520.2
  Bottom Layer w12: R211_A4.1@9309.62,4034.03 R211_A4.1@9311.02,4035.43
TS5_A1: C116_A1.1 J2_A1.3 R210_A1.1 U3_A1.15 | length 2663.5
  Top Layer w7: v1(2394.98,3531.63) 2419.27,3555.91 2427.17,3555.91 2442.05,3570.79 2460.38,3570.79 2468.17,3578.58 2468.17,3581.73 2482.39,3595.94 J2_A1.3@2482.39,3647.12
  Top Layer w8: v1(2417.04,3809.06) 2482.39,3743.71 2482.39,3702.86 J2_A1.3@2480.32,3700.79
  Bottom Layer w7: C116_A1.1@2405.97,3593.93 2405.97,3590 2387.76,3571.79 2387.76,3542.91 2394.98,3535.69 2394.98,3470.2 2229,3304.22 2229,1705.02 2271,1663.02 2420.45,1663.02 2432.87,1675.44 2456.91,1675.44 2493.16,1711.69 2493.16,1747.28 U3_A1.15@2491.9,1748.54
  Bottom Layer w8: R210_A1.1@2417.04,3860.24 2417.04,3813.27 v1@2421.26,3809.06
TS5_A2: C116_A2.1 J2_A2.3 R210_A2.1 U3_A2.15 | length 2670.5
  Top Layer w7: v1(4689.99,3531.63) 4714.28,3555.91 4722.19,3555.91 4737.06,3570.79 4755.4,3570.79 4763.19,3578.58 4763.19,3581.73 4777.41,3595.94 J2_A2.3@4777.41,3647.12
  Top Layer w8: v1(4720.19,3818.9) 4777.41,3761.68 4777.41,3704.57 J2_A2.3@4773.62,3700.79
  Bottom Layer w7: C116_A2.1@4700.98,3593.93 4700.98,3590 4682.77,3571.79 4682.77,3542.91 4689.99,3535.69 v1(4689.99,3531.63) 4521.81,3363.44 4521.81,1707.23 4566.01,1663.02 4715.47,1663.02 4727.89,1675.44 4751.93,1675.44 4788.18,1711.69 4788.18,1747.28 U3_A2.15@4786.92,1748.54
  Bottom Layer w8: v1(4720.19,3818.9) 4720.19,3863.89 R210_A2.1@4724.41,3868.11
TS5_A3: C116_A3.1 J2_A3.3 R210_A3.1 U3_A3.15 | length 2661.7
  Top Layer w7: v1(7026.59,3534.83) 7050.88,3559.12 7058.78,3559.12 7073.66,3574 7091.99,3574 7099.79,3581.79 7099.79,3584.93 7114,3599.15 J2_A3.3@7114,3650.33
  Top Layer w8: v1(7046.63,3813.3) 7114,3745.93 7114,3711.29 7114.66,3710.63 J2_A3.3@7116.14,3710.63
  Bottom Layer w7: C116_A3.1@7037.58,3597.14 7037.58,3593.2 7019.37,3574.99 7019.37,3546.11 7026.59,3538.9 v1(7026.59,3534.83) 6845.14,3353.39 6845.14,1723.7 6902.61,1666.23 7052.06,1666.23 7064.48,1678.65 7088.52,1678.65 7124.77,1714.9 7124.77,1750.49 U3_A3.15@7123.51,1751.75
  Bottom Layer w8: R210_A3.1@7045.84,3860.24 7045.84,3819.77 7046.71,3818.9 v1@7047.24,3818.9
TS5_A4: C116_A4.1 J2_A4.3 R210_A4.1 U3_A4.15 | length 2689.1
  Top Layer w7: v1(9346.82,3531.63) 9371.11,3555.91 9379.01,3555.91 9393.89,3570.79 9412.22,3570.79 9420.02,3578.58 9420.02,3581.73 9434.23,3595.94 J2_A4.3@9434.23,3647.12 ; v1(9377.11,3828.74) 9434.23,3771.62 J2_A4.3@9434.23,3705.89
  Top Layer w12: J2_A4.3@9429.13,3700.79 J2_A4.3@9434.23,3705.89
  Bottom Layer w7: C116_A4.1@9357.81,3593.93 9357.81,3590 9339.6,3571.79 9339.6,3542.91 9346.82,3535.69 v1(9346.82,3531.63) 9259.7,3444.5 9259.7,3407.84 9167.98,3316.12 9167.98,1717.88 9222.84,1663.02 9372.29,1663.02 9384.71,1675.44 9408.75,1675.44 9445,1711.69 9445,1747.28 U3_A4.15@9443.74,1748.54 ; v1(9377.11,3828.74) R210_A4.1@9377.11,3875.14
  Bottom Layer w12: R210_A4.1@9377.11,3875.14 R210_A4.1@9379.92,3877.95
TS6_A1: C111_A1.1 J2_A1.24 R209_A1.1 U3_A1.14 | length 2903.3
  Top Layer w7: v1(2430.06,3532) 2453.97,3555.91 2466.54,3555.91 2467.54,3556.91 2485.87,3556.91 2507.54,3578.58 2507.54,3581.73 2521.76,3595.94 J2_A1.24@2521.76,3647.12
  Top Layer w8: v1(2417.04,3966.54) 2417.04,3848.41 2521.76,3743.69 2521.76,3702.86 J2_A1.24@2519.68,3700.79 ; J2_A1.24@2519.68,3681.1 J2_A1.24@2521.76,3683.18
  Bottom Layer w7: v1(2430.06,3532) 2430.06,3484.24 2243.87,3298.06 2243.87,1711.18 2277.16,1677.89 2414.29,1677.89 2426.71,1690.31 2439.7,1690.31 2460.95,1711.57 2460.95,1743.19 U3_A1.14@2466.31,1748.54 ; v1@2431.1,3533.46 2431.52,3533.46 2450.26,3552.21 2450.26,3656.78 2464.3,3670.81 2470.03,3670.81 2479.2,3679.99 C111_A1.1@2479.2,3702.2
  Bottom Layer w8: v1@2417.04,3970.75 R209_A1.1@2417.04,4015.75
TS6_A2: C111_A2.1 J2_A2.24 R209_A2.1 U3_A2.14 | length 2897
  Top Layer w7: v1(4725.07,3532) 4748.99,3555.91 4761.56,3555.91 4762.55,3556.91 4780.89,3556.91 4802.56,3578.58 4802.56,3581.73 4816.78,3595.94 J2_A2.24@4816.78,3647.12
  Top Layer w8: v1(4720.19,3966.54) 4720.19,3858.25 4816.78,3761.67 4816.78,3704.57 J2_A2.24@4812.99,3700.79
  Bottom Layer w7: v1(4725.07,3532) 4536.68,3343.61 4536.68,1713.39 4572.17,1677.89 4709.3,1677.89 4721.72,1690.31 4734.71,1690.31 4755.97,1711.57 4755.97,1743.19 U3_A2.14@4761.33,1748.54 ; v1@4726.12,3533.46 4726.54,3533.46 4745.28,3552.21 4745.28,3656.78 4759.31,3670.81 4765.04,3670.81 4774.22,3679.99 C111_A2.1@4774.22,3702.2
  Bottom Layer w8: v1(4720.19,3966.54) 4720.19,4004 4722.1,4005.91 R209_A2.1@4724.41,4005.91
TS6_A3: C111_A3.1 J2_A3.24 R209_A3.1 U3_A3.14 | length 2910.5
  Top Layer w7: v1(7061.67,3535.21) 7085.58,3559.12 7098.15,3559.12 7099.15,3560.12 7117.48,3560.12 7139.16,3581.79 7139.16,3584.93 7153.37,3599.15 J2_A3.24@7153.37,3650.33
  Top Layer w8: v1(7046.63,3970.78) 7046.63,3854.06 7153.37,3747.32 7153.37,3711.29 7154.03,3710.63 J2_A3.24@7155.51,3710.63
  Bottom Layer w7: v1(7061.67,3535.21) 6860.02,3333.55 6860.02,1729.86 6908.77,1681.1 7045.9,1681.1 7058.32,1693.52 7071.31,1693.52 7092.56,1714.78 7092.56,1746.39 U3_A3.14@7097.92,1751.75 ; v1@7062.72,3536.67 7063.13,3536.67 7081.88,3555.41 7081.88,3659.99 7095.91,3674.02 7101.64,3674.02 7110.82,3683.2 C111_A3.1@7110.82,3705.41
  Bottom Layer w8: R209_A3.1@7045.84,4021.65 7045.84,3977.25 7046.71,3976.38 v1@7047.24,3976.38
TS6_A4: C111_A4.1 J2_A4.24 R209_A4.1 U3_A4.14 | length 2953.7
  Top Layer w7: v1(9377.11,3986.22) 9419.74,3943.59 9419.74,3818.45 9473.6,3764.59 J2_A4.24@9473.6,3686.2 ; v1(9381.9,3532) 9405.81,3555.91 9418.38,3555.91 9419.38,3556.91 9437.71,3556.91 9459.39,3578.58 9459.39,3581.73 9473.6,3595.94 J2_A4.24@9473.6,3647.12
  Top Layer w12: J2_A4.24@9468.5,3681.1 J2_A4.24@9473.6,3686.2
  Bottom Layer w7: v1(9377.11,3986.22) R209_A4.1@9377.11,4032.62 ; v1(9381.9,3532) 9280.94,3431.04 9280.94,3408.05 9182.85,3309.96 9182.85,1724.04 9229,1677.89 9366.13,1677.89 9378.55,1690.31 9391.54,1690.31 9412.79,1711.57 9412.79,1743.19 U3_A4.14@9418.15,1748.54 ; v1@9382.94,3533.46 9383.36,3533.46 9402.11,3552.21 9402.11,3656.78 9416.14,3670.81 9421.87,3670.81 9431.05,3679.99 C111_A4.1@9431.05,3702.2
  Bottom Layer w12: R209_A4.1@9377.11,4032.62 R209_A4.1@9379.92,4035.43
TS7_A1: C108_A1.1 J2_A1.4 R208_A1.1 U3_A1.13 | length 2586.1
  Top Layer w7: v1(2465.14,3532.1) 2500.43,3532.1 2546.91,3578.58 2546.91,3581.73 2561.13,3595.94 J2_A1.4@2561.13,3647.12
  Top Layer w8: v1(2488.75,3809.06) 2561.13,3736.68 2561.13,3693.02 J2_A1.4@2559.06,3690.94
  Bottom Layer w7: U3_A1.13@2440.72,1748.54 2440.94,1748.32 2440.94,1712.6 2433.53,1705.19 2420.55,1705.19 2408.13,1692.77 2283.32,1692.77 2258.75,1717.34 2258.75,3291.9 2465.14,3498.29 2465.14,3590.61 2474.98,3590.61 C108_A1.1@2478.31,3593.93
  Bottom Layer w8: R208_A1.1@2488.75,3860.24 2488.75,3810.46 v1@2490.16,3809.06
TS7_A2: C108_A2.1 J2_A2.4 R208_A2.1 U3_A2.13 | length 2570.1
  Top Layer w7: v1(4759.87,3532.38) 4760.15,3532.1 4795.45,3532.1 4841.93,3578.58 4841.93,3581.73 4856.15,3595.94 J2_A2.4@4856.15,3647.12
  Top Layer w8: v1(4787.96,3822.84) 4856.15,3754.65 4856.15,3706.85 J2_A2.4@4862.2,3700.79
  Bottom Layer w7: U3_A2.13@4735.74,1748.54 4735.96,1748.32 4735.96,1712.6 4728.55,1705.19 4715.56,1705.19 4703.14,1692.77 4610.84,1692.77 4595.25,1692.77 4551.56,1736.47 4551.56,3324.07 v1(4759.87,3532.38) ; v1@4760.15,3532.38 4760.15,3536.73 4765.01,3541.58 4765.01,3585.62 C108_A2.1@4773.32,3593.93
  Bottom Layer w8: v1(4787.96,3822.84) 4789.93,3824.81 4789.93,3864.73 R208_A2.1@4791.9,3866.7
TS7_A3: C108_A3.1 J2_A3.4 R208_A3.1 U3_A3.13 | length 2575.4
  Top Layer w7: v1(7096.75,3535.31) 7132.04,3535.31 7178.53,3581.79 7178.53,3584.93 7192.74,3599.15 J2_A3.4@7192.74,3650.33
  Top Layer w8: v1(7119.75,3813.3) 7192.74,3740.31 7192.74,3711.29 7193.41,3710.63 J2_A3.4@7194.88,3710.63
  Bottom Layer w7: U3_A3.13@7072.33,1751.75 7072.56,1751.53 7072.56,1715.8 7065.15,1708.4 7052.16,1708.4 7039.74,1695.98 6914.93,1695.98 6874.89,1736.02 6874.89,3313.45 v1(7096.75,3535.31) 7096.75,3593.81 7106.59,3593.81 C108_A3.1@7109.92,3597.14
  Bottom Layer w8: v1@7116.14,3818.9 7118.95,3821.71 R208_A3.1@7118.95,3860.24
TS7_A4: C108_A4.1 J2_A4.4 R208_A4.1 U3_A4.13 | length 2607.9
  Top Layer w7: v1(9416.98,3532.1) 9452.27,3532.1 9498.76,3578.58 9498.76,3581.73 9512.97,3595.94 J2_A4.4@9512.97,3647.12 ; v1(9444.62,3828.76) 9512.97,3760.4 J2_A4.4@9512.97,3696.04
  Top Layer w12: J2_A4.4@9507.87,3690.94 J2_A4.4@9512.97,3696.04
  Bottom Layer w7: U3_A4.13@9392.56,1748.54 9392.79,1748.32 9392.79,1712.6 9385.38,1705.19 9372.39,1705.19 9359.97,1692.77 9235.16,1692.77 9197.72,1730.2 9197.72,3303.8 9305.92,3411.99 9305.92,3421.04 v1(9416.98,3532.1) 9416.98,3590.61 9426.82,3590.61 C108_A4.1@9430.15,3593.93 ; v1(9444.62,3828.76) R208_A4.1@9444.61,3872.32
TS8_A1: C137_A1.1 J2_A1.5 R221_A1.1 U2_A1.5 | length 3216
  Top Layer w7: U2_A1.5@2466.31,1524.15 2466.31,1485.66 2461.38,1480.73 2460.69,1480.73 2417.07,1437.12 2415.4,1437.12 2412.84,1434.56 2366.76,1434.56 2349.04,1452.29 2340.41,1452.29 2313.97,1478.73 2313.97,1511.89 2190.88,1634.98 2190.88,3310.87 2345.24,3465.23 2567.97,3465.23 v1(2660.28,3557.53) 2660.28,3561.6 2650.15,3571.72 2650.15,3636.84 J2_A1.5@2639.87,3647.12
  Top Layer w8: v1(2488.75,3966.54) 2488.75,3906.08 2639.87,3754.97 2639.87,3693.02 J2_A1.5@2637.8,3690.94 ; J2_A1.5@2637.8,3681.1 J2_A1.5@2639.87,3683.18
  Bottom Layer w7: C137_A1.1@2659.32,3598.72 2660.28,3597.76 v1@2660.28,3557.88
  Bottom Layer w8: R221_A1.1@2488.75,4015.75 2488.75,3967.94 v1@2490.16,3966.54
TS8_A2: C137_A2.1 J2_A2.5 R221_A2.1 U2_A2.5 | length 3215.1
  Top Layer w7: U2_A2.5@4763.91,1527.5 4761.33,1524.91 4761.33,1485.66 4756.4,1480.73 4755.7,1480.73 4733,1458.03 4733,1451.98 4710.3,1429.28 4679.44,1429.28 4670.99,1437.74 4649.97,1437.74 4608.98,1478.73 4608.98,1537.63 4474.04,1672.58 4474.04,3290.88 4644.34,3461.18 4858.95,3461.18 4929.41,3531.65 4929.41,3551.45 v1(4931.1,3553.15) 4931.1,3643.34 J2_A2.5@4934.89,3647.12
  Top Layer w8: v1(4791.9,3966.54) 4791.9,3902.02 4934.89,3759.03 4934.89,3704.57 J2_A2.5@4931.1,3700.79
  Bottom Layer w7: v1(4931.1,3553.15) 4931.1,3553.71 4946.03,3568.63 4946.03,3590.41 C137_A2.1@4954.34,3598.72
  Bottom Layer w8: v1(4791.9,3966.54) 4791.9,4014.34 R221_A2.1@4793.31,4015.75
TS8_A3: C137_A3.1 J2_A3.5 R221_A3.1 U2_A3.5 | length 3270.1
  Top Layer w7: U2_A3.5@7101.36,1531 7097.92,1527.57 7097.92,1488.87 7093,1483.94 7092.3,1483.94 7067.64,1459.28 7067.64,1453.94 7042.98,1429.28 7012.11,1429.28 7000.45,1440.94 6986.57,1440.94 6939.69,1487.83 6939.69,1547.87 6800.52,1687.04 6800.52,3314.53 6800.52,3324.37 6961.07,3484.91 6970.91,3484.91 7234.91,3484.91 7287.99,3537.99 7287.99,3546.95 7273.62,3561.31 7273.62,3648.19 J2_A3.5@7271.48,3650.33
  Top Layer w8: v1(7119.75,3970.78) 7119.75,3910.12 7271.48,3758.38 7271.48,3711.29 7270.82,3710.63 J2_A3.5@7263.78,3710.63
  Bottom Layer w7: v1(7273.62,3562.99) 7276.49,3565.86 7282.08,3565.86 7291.89,3575.68 7291.89,3600.97 C137_A3.1@7290.94,3601.93
  Bottom Layer w8: v1@7116.14,3976.38 7118.95,3979.19 R221_A3.1@7118.95,4021.65
TS8_A4: C137_A4.1 J2_A4.5 R221_A4.1 U2_A4.5 | length 3212.6
  Top Layer w7: U2_A4.5@9422.5,1524.55 9418.15,1520.2 9418.15,1485.66 9413.23,1480.73 9412.53,1480.73 9389.17,1457.37 9389.17,1452.64 9365.81,1429.28 9334.94,1429.28 9326.49,1437.74 9306.8,1437.74 9265.81,1478.73 9265.81,1511.89 9139.39,1638.31 9139.39,3290.88 9299.86,3451.34 9503.14,3451.34 9586.61,3534.81 9586.61,3642.02 J2_A4.5@9591.71,3647.12 ; v1(9444.6,3986.22) 9444.6,3914.46 9591.71,3767.35 J2_A4.5@9591.71,3705.53
  Top Layer w12: J2_A4.5@9591.71,3705.53 J2_A4.5@9596.46,3700.79
  Bottom Layer w7: v1(9444.6,3986.22) R221_A4.1@9444.6,4029.81 ; v1(9586.61,3562.99) 9589.49,3565.86 9589.49,3573.1 9611.17,3594.78 C137_A4.1@9611.17,3598.72
  Bottom Layer w12: R221_A4.1@9438.98,4035.43 R221_A4.1@9444.6,4029.81
TS9_A1: C131_A1.1 J2_A1.26 R220_A1.1 U2_A1.4 | length 3309.7
  Top Layer w7: U2_A1.4@2440.72,1524.15 2440.72,1481.8 2410.91,1451.99 2409.24,1451.99 2406.68,1449.44 2372.92,1449.44 2355.2,1467.16 2346.57,1467.16 2328.84,1484.89 2328.84,1518.05 2205.75,1641.14 2205.75,3304.71 2351.4,3450.35 2588.18,3450.35 v1(2695.36,3557.53) 2679.24,3573.65 J2_A1.26@2679.24,3647.12
  Top Layer w8: v1(2560.46,3966.54) 2559.06,3965.13 2559.06,3907.48 2696.85,3769.69 2696.85,3730.31 J2_A1.26@2677.17,3710.63 ; J2_A1.26@2677.17,3681.1 J2_A1.26@2689.02,3692.96
  Bottom Layer w7: v1(2695.36,3557.53) 2695.36,3602.26 2684.01,3613.61 2684.01,3653.92 2704.68,3674.59 2717.26,3674.59 2723.12,3680.44 C131_A1.1@2723.12,3706.99
  Bottom Layer w8: v1@2559.06,3966.54 2560.46,3967.94 R220_A1.1@2560.46,4015.75
TS9_A2: C131_A2.1 J2_A2.26 R220_A2.1 U2_A2.4 | length 3299.2
  Top Layer w7: U2_A2.4@4738.32,1527.5 4735.74,1524.91 4735.74,1481.8 4718.13,1464.2 4718.13,1458.14 4704.14,1444.15 4685.6,1444.15 4677.15,1452.61 4656.14,1452.61 4623.86,1484.89 4623.86,1543.79 4488.91,1678.74 4488.91,3284.72 4648.54,3444.34 4874.6,3444.34 4966.18,3535.92 4966.18,3557.21 4974.26,3565.28 J2_A2.26@4974.26,3647.12
  Top Layer w8: v1(4863.61,3966.54) 4863.61,3903.31 4983.51,3783.41 4983.51,3723.67 J2_A2.26@4970.47,3710.63
  Bottom Layer w7: v1(4966.18,3553.15) 4990.37,3577.34 4990.37,3602.26 4979.02,3613.61 4979.02,3653.92 4999.69,3674.59 5012.28,3674.59 5018.14,3680.44 C131_A2.1@5018.14,3706.99
  Bottom Layer w8: R220_A2.1@4862.2,4015.75 4863.61,4014.34 v1(4863.61,3966.54)
TS9_A3: C131_A3.1 J2_A3.26 R220_A3.1 U2_A3.4 | length 3340.7
  Top Layer w7: U2_A3.4@7075.77,1531 7072.33,1527.57 7072.33,1485.01 7052.76,1465.44 7052.76,1460.1 7036.81,1444.15 7018.28,1444.15 7006.61,1455.82 6992.73,1455.82 6954.56,1493.99 6954.56,1554.03 6815.39,1693.2 6815.39,3308.36 6815.39,3318.21 6967.23,3470.04 7248.22,3470.04 7313.35,3535.17 v1@7313.35,3562.99 ; J2_A3.26@7310.85,3650.33 7313.35,3647.84 7313.35,3563.35 v1@7312.99,3562.99
  Top Layer w8: v1(7192.86,3970.78) 7192.86,3919.12 7288.86,3823.12 7288.86,3808.73 7326.03,3771.56 7326.03,3738.08 7315.24,3727.29 7315.24,3711.29 J2_A3.26@7314.58,3710.63
  Bottom Layer w7: v1@7313.35,3562.99 7313.35,3566.15 7326.97,3579.78 7326.97,3605.46 7315.62,3616.81 7315.62,3657.13 7336.29,3677.79 7348.87,3677.79 7354.73,3683.65 C131_A3.1@7354.73,3710.2
  Bottom Layer w8: R220_A3.1@7192.07,4021.65 7192.07,3977.25 7192.94,3976.38 v1@7194.88,3976.38
  other v1: 7311.75,3562.99
TS9_A4: C131_A4.1 J2_A4.26 R220_A4.1 U2_A4.4 | length 3308.6
  Top Layer w7: U2_A4.4@9395.28,1521.27 9395.28,1484.52 9374.29,1463.53 9374.29,1458.8 9359.64,1444.15 9341.11,1444.15 9320.54,1464.72 9305.6,1464.72 9285.03,1485.29 9285.03,1513.71 9154.26,1644.47 9154.26,3284.72 9306.02,3436.47 9528.99,3436.47 9625.98,3533.46 v1(9625.98,3562.99) 9625.98,3642.02 J2_A4.26@9631.08,3647.12 ; v1(9510.69,3986.22) 9510.69,3894.83 9645.67,3759.84 9645.67,3726.95 9625.98,3707.27 J2_A4.26@9625.98,3700.79
  Bottom Layer w7: R220_A4.1@9507.87,4035.43 9510.69,4032.62 v1(9510.69,3986.22) ; v1(9625.98,3562.99) 9647.2,3584.21 9647.2,3602.26 9635.85,3613.61 9635.85,3653.92 9656.52,3674.59 9669.1,3674.59 9674.96,3680.44 C131_A4.1@9674.96,3706.99
TS10_A1: C127_A1.1 J2_A1.6 R219_A1.1 U2_A1.2 | length 3048.6
  Top Layer w7: U2_A1.2@2389.54,1524.15 2384.18,1518.79 2384.18,1491.05 2376.38,1483.24 2351.52,1483.24 2343.72,1491.05 2343.72,1524.21 2220.63,1647.3 2220.63,3298.55 2357.56,3435.48 2608.38,3435.48 v1(2730.44,3557.53) 2730.44,3559.83 2718.61,3571.66 J2_A1.6@2718.61,3647.12
  Top Layer w8: v1(2632.17,3966.54) 2632.17,3856.81 2718.61,3770.37 J2_A1.6@2718.61,3698.71
  Bottom Layer w7: C127_A1.1@2721.82,3598.72 2720.21,3597.11 2720.21,3572.18 v1@2730.44,3561.94
  Bottom Layer w8: v1@2627.95,3966.54 2632.17,3970.75 R219_A1.1@2632.17,4015.75
TS10_A2: C127_A2.1 J2_A2.6 R219_A2.1 U2_A2.2 | length 3034.2
  Top Layer w7: U2_A2.2@4687.14,1527.5 4681.78,1522.14 4681.78,1494.4 4673.98,1486.6 4649.12,1486.6 4638.73,1496.99 4638.73,1549.95 4503.78,1684.9 4503.78,3278.55 4654.7,3429.47 4896,3429.47 4999.57,3533.03 4999.57,3551.45 v1(5001.26,3553.15) 5001.26,3557.21 5013.63,3569.58 J2_A2.6@5013.63,3647.12
  Top Layer w8: v1(4935.32,3966.54) 4935.32,3854.05 5009.84,3779.53 J2_A2.6@5009.84,3710.63
  Bottom Layer w7: v1(5001.26,3553.15) 5001.26,3555.64 5015.22,3569.6 5015.22,3597.11 C127_A2.1@5016.84,3598.72
  Bottom Layer w8: R219_A2.1@4931.1,4015.75 4935.32,4011.53 v1(4935.32,3966.54)
TS10_A3: C127_A3.1 J2_A3.6 R219_A3.1 U2_A3.2 | length 3075
  Top Layer w7: U2_A3.2@7024.58,1531 7019.23,1525.64 7019.23,1497.9 7011.42,1490.1 6986.57,1490.1 6969.44,1507.23 6969.44,1560.19 6830.27,1699.36 6830.27,3302.2 6830.27,3312.05 6973.39,3455.17 6983.23,3455.17 7254.38,3455.17 7351.11,3551.9 7351.11,3553.61 7356.43,3558.93 v1@7356.43,3562.99 ; J2_A3.6@7350.22,3650.33 7352.36,3648.19 v1@7352.36,3558.93
  Top Layer w8: v1(7265.98,3970.78) 7305.28,3931.48 7305.28,3814.76 7350.22,3769.82 7350.22,3702.93 J2_A3.6@7352.36,3700.79
  Bottom Layer w7: v1@7352.36,3562.99 7352.36,3600.86 C127_A3.1@7353.43,3601.93
  Bottom Layer w8: v1@7263.78,3976.38 7264.31,3976.38 7265.19,3977.25 R219_A3.1@7265.19,4021.65
  other v1: 7349.87,3562.99
TS10_A4: C127_A4.1 J2_A4.6 R219_A4.1 U2_A4.2 | length 3033.5
  Top Layer w7: U2_A4.2@9345.73,1524.55 9340.37,1519.19 9340.37,1491.45 9332.56,1483.65 9307.71,1483.65 9299.9,1491.45 9299.9,1519.87 9169.14,1650.63 9169.14,3278.55 9312.18,3421.59 9543.64,3421.59 9660.04,3537.99 9660.04,3560.8 v1(9662.23,3562.99) ; v1(9580.99,3986.22) 9580.99,3863.18 9662.1,3782.06 9662.1,3708.58 9669.9,3700.79 J2_A4.6@9675.2,3700.79 ; v1@9665.35,3571.35 9665.35,3642.02 J2_A4.6@9670.45,3647.12
  Bottom Layer w7: v1(9580.99,3986.22) R219_A4.1@9580.99,4031.22 ; v1@9665.35,3572.83 9665.35,3590.41 C127_A4.1@9673.66,3598.72
  Bottom Layer w12: R219_A4.1@9576.77,4035.43 R219_A4.1@9580.99,4031.22
TS11_A1: C122_A1.1 J2_A1.27 R218_A1.1 U2_A1.1 | length 2884.2
  Top Layer w7: U2_A1.1@2363.95,1524.15 2363.95,1534.91 2358.59,1540.27 2348.69,1540.27 2235.5,1653.46 2235.5,3292.39 2363.72,3420.61 2625.16,3420.61 2757.98,3553.43 v1@2757.98,3557.53 ; J2_A1.27@2757.98,3647.12 2757.98,3569.13 2765.52,3561.6 v1(2765.52,3557.53)
  Top Layer w8: v1(2708.08,3813.26) 2755.91,3765.43 J2_A1.27@2755.91,3710.63
  Bottom Layer w7: v1(2765.52,3557.53) 2765.52,3561.6 2761.13,3565.98 2761.13,3678.36 2785.82,3703.05 C122_A1.1@2785.82,3706.99
  Bottom Layer w8: R218_A1.1@2706.69,3858.27 2707.39,3857.57 2707.39,3813.95 v1(2708.08,3813.26)
TS11_A2: C122_A2.1 J2_A2.27 R218_A2.1 U2_A2.1 | length 2912.6
  Top Layer w7: U2_A2.1@4661.55,1527.5 4661.55,1548.17 4518.66,1691.06 4518.66,3272.39 4660.86,3414.59 4917.39,3414.59 5034.45,3531.65 5034.45,3551.35 5053,3569.9 J2_A2.27@5053,3647.12
  Top Layer w8: v1(5009.84,3818.9) 5053,3775.74 5053,3704.57 J2_A2.27@5049.21,3700.79
  Bottom Layer w7: v1(5036.24,3553.15) 5055.82,3572.73 5055.82,3678.04 5080.83,3703.05 C122_A2.1@5080.83,3706.99
  Bottom Layer w8: v1(5009.84,3818.9) R218_A2.1@5009.84,3870.08 R218_A2.1@5009.84,3871.2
